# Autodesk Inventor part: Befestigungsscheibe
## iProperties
Created: 2005-12
Part Number: Befestigungsscheibe
Document SubType Name: Modeling
Designer: Kumpf
Manufacturer: Standard
Standards Organization: Custom
Material: Stahl (schweißbar)
Author: Kumpf
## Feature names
1. Extrusion1
2. Bohrung1 [Hole]
3. Fase1 [Chamfer]
